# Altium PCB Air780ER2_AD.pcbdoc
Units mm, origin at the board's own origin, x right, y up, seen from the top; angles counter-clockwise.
Board outline 30.8 x 32.7 mm, 4 copper layers (Top Layer, 内层 2, 内层 3, Bottom Layer); 1 components, 0 nets, 54 pads, 0 vias.
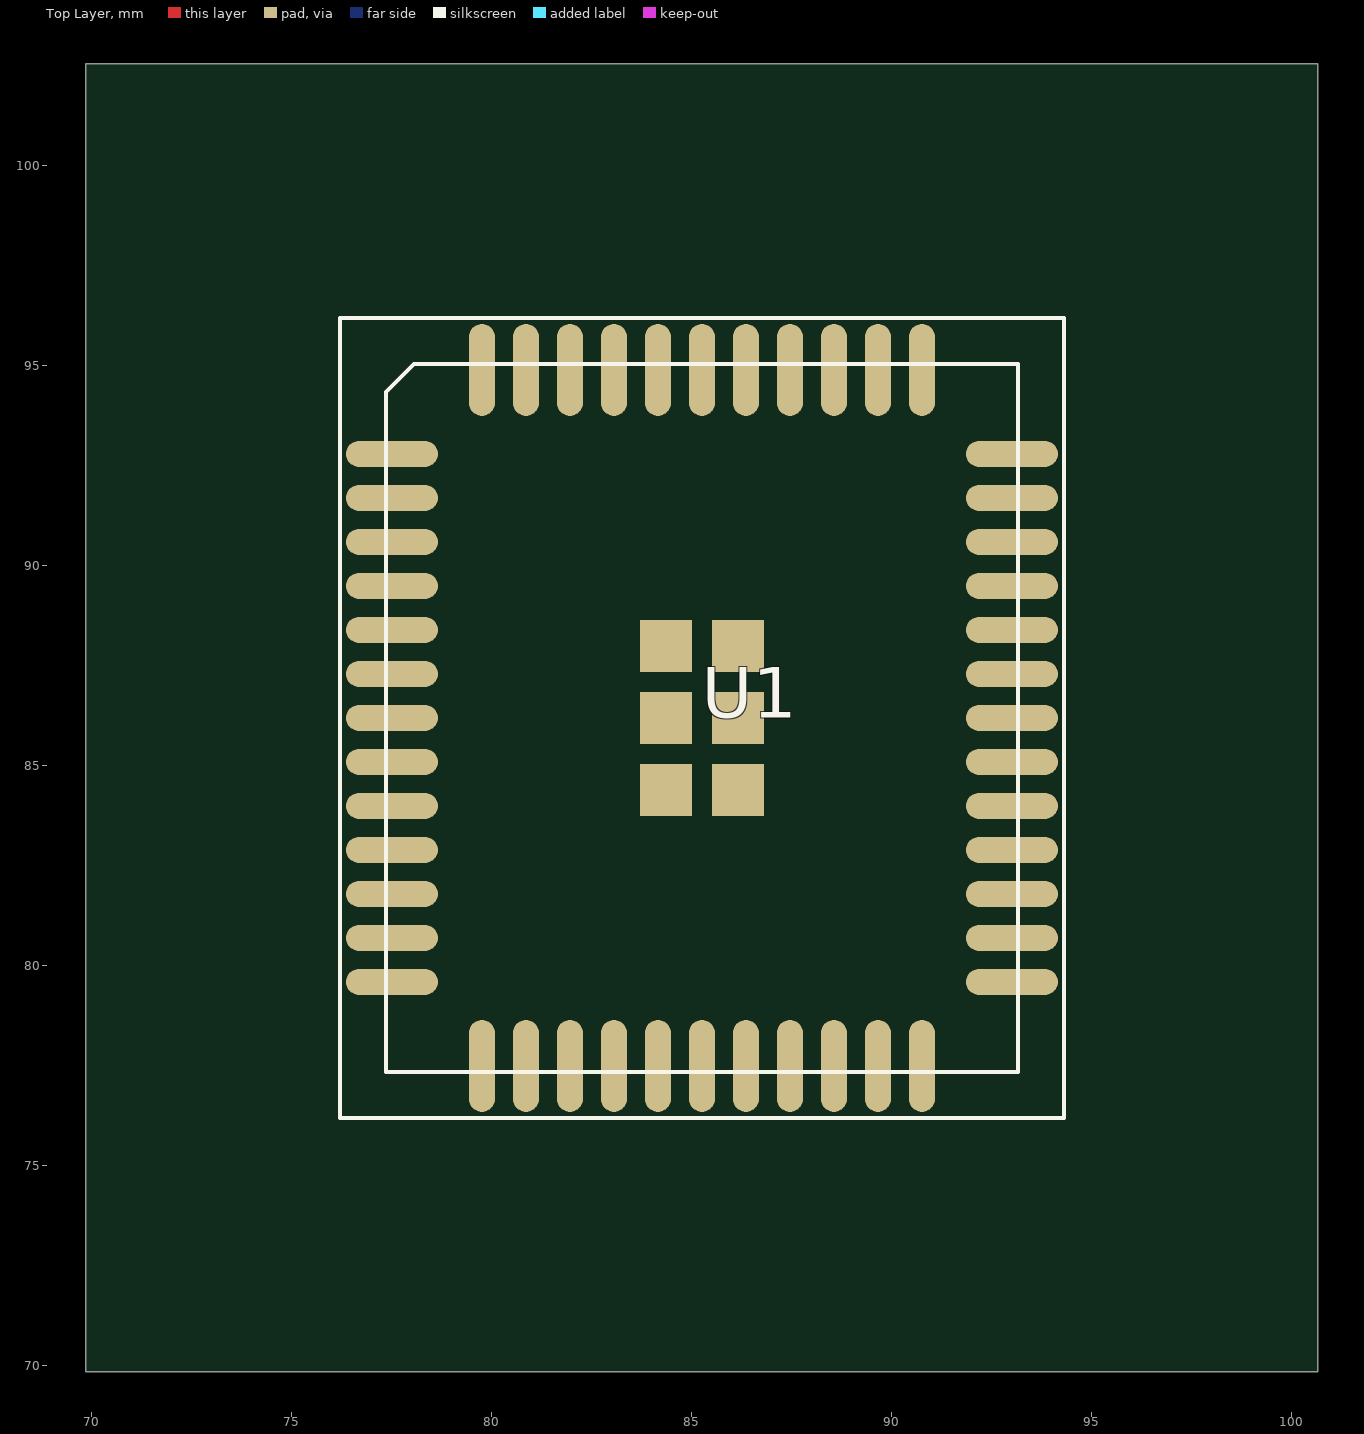
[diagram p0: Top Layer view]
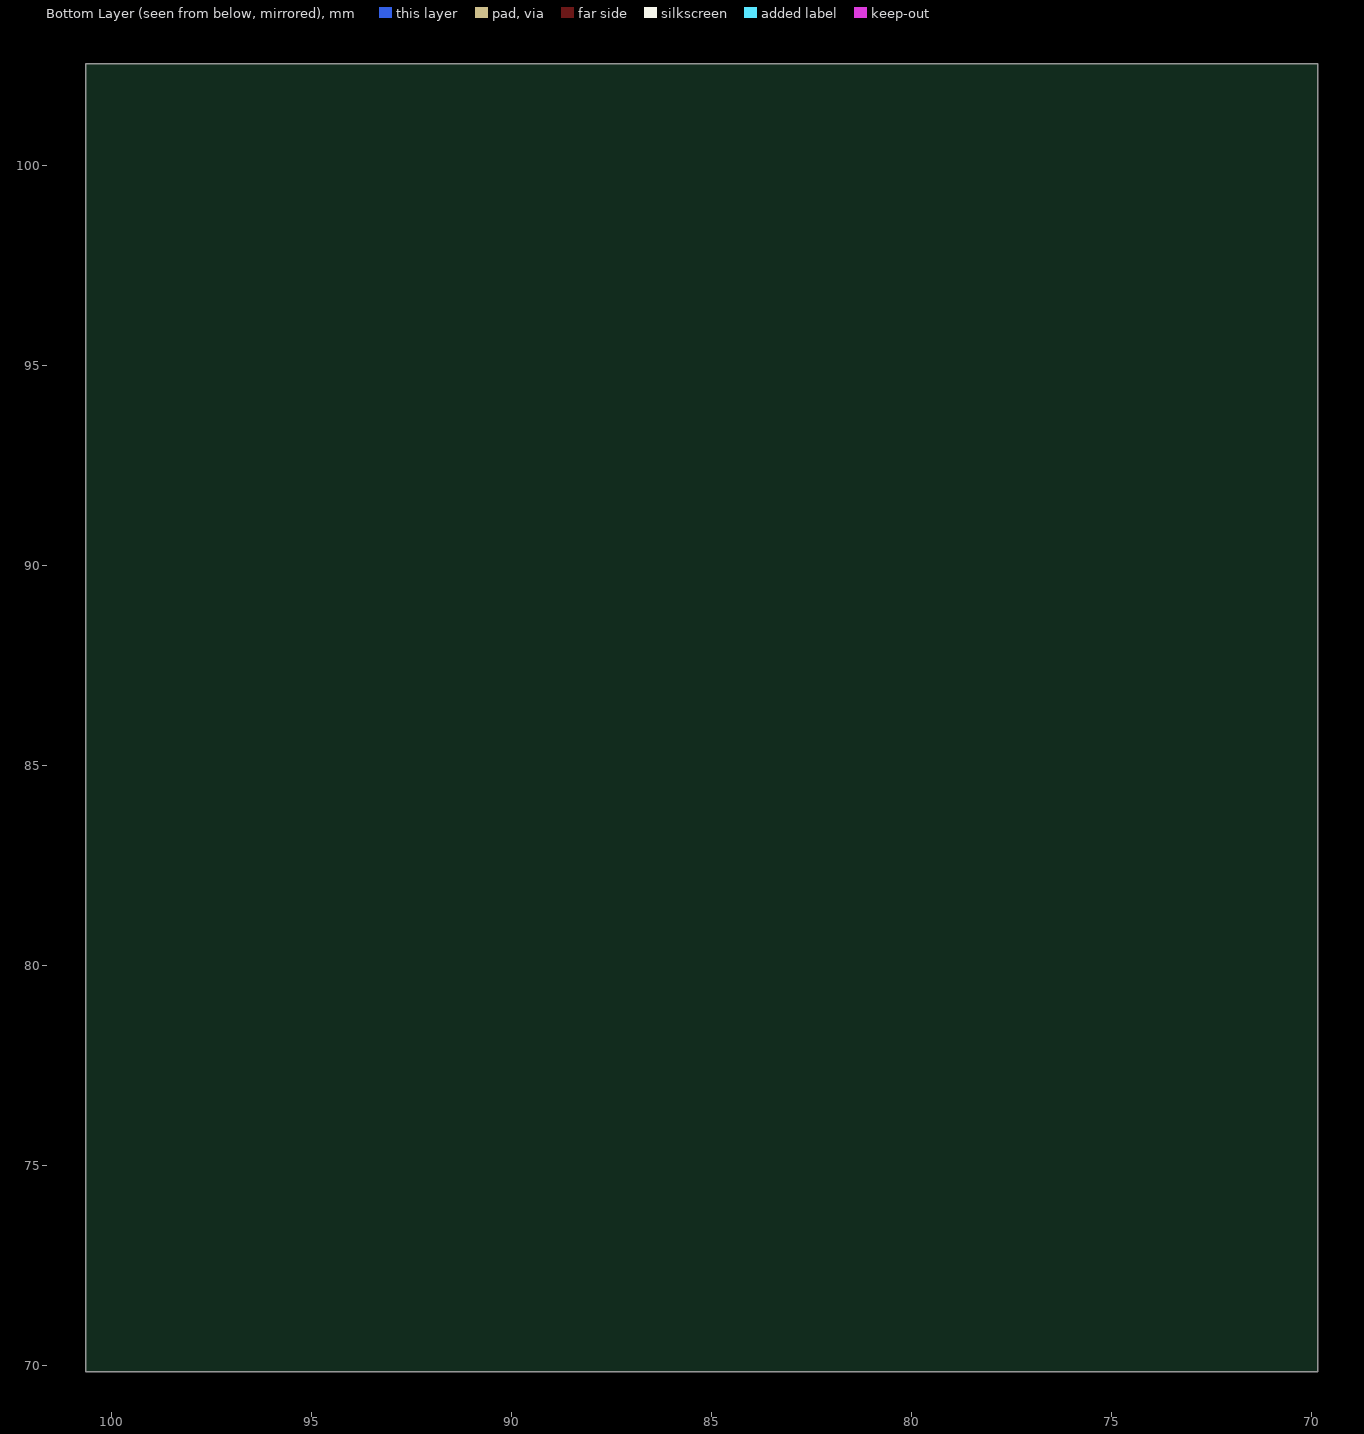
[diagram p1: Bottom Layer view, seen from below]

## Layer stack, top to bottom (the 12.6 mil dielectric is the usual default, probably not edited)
Top Layer: signal copper (thickness not stored)
Dielectric: dielectric 0.32, FR-4, Dk 4.8
内层 2: signal copper (thickness not stored)
Dielectric: dielectric 0.32, FR-4, Dk 4.8
内层 3: signal copper (thickness not stored)
Dielectric: dielectric 0.32, FR-4, Dk 4.8
Bottom Layer: signal copper (thickness not stored)

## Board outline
100.65,69.85 69.85,69.85 69.85,102.55 100.65,102.55

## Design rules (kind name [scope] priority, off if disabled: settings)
BoardOutlineClearance safeClearance [All] p0: genericclearance=0.254 ignorepadtopadclearanceinfootprint=FALSE except(0: Region-OutlineEdge Poly-OutlineEdge Text-OutlineEdge Sheet-OutlineEdge Hole-OutlineEdge Track-CutoutEdge SMDPad-CutoutEdge THPad-CutoutEdge Via-CutoutEdge Fill-CutoutEdge Region-CutoutEdge Poly-CutoutEdge Text-CutoutEdge Sheet-CutoutEdge Hole-CutoutEdge Arc-SplitContinuation Track-SplitContinuation SMDPad-SplitContinuation THPad-SplitContinuation Via-SplitContinuation Fill-SplitContinuation Poly-SplitContinuation Region-SplitContinuation Text-SplitContinuation; 0.152: Track-OutlineEdge SMDPad-OutlineEdge THPad-OutlineEdge Via-OutlineEdge Fill-OutlineEdge)
Clearance safeClearance [All] p1: gap=0.178 ignorepadtopadclearanceinfootprint=FALSE except(0: Region-Track Poly-Track Region-SMDPad Poly-SMDPad Region-THPad Poly-THPad Region-Via Poly-Via Region-Fill Poly-Fill Text-Fill Track-Region SMDPad-Region THPad-Region Via-Region Fill-Region Region-Region Poly-Region Text-Region Sheet-Region Hole-Region Track-Poly SMDPad-Poly THPad-Poly Via-Poly Fill-Poly Region-Poly Poly-Poly Text-Poly Sheet-Poly Hole-Poly Fill-Text Region-Text Poly-Text Text-Text Sheet-Text Hole-Text Region-Sheet Poly-Sheet Text-Sheet Sheet-Sheet Hole-Sheet Region-Hole Poly-Hole Text-Hole Sheet-Hole; 0.152: Track-Track SMDPad-Track THPad-Track Via-Track Fill-Track Text-Track Sheet-Track Hole-Track Track-SMDPad SMDPad-SMDPad THPad-SMDPad Via-SMDPad Fill-SMDPad Text-SMDPad Sheet-SMDPad Hole-SMDPad Track-THPad SMDPad-THPad THPad-THPad Via-THPad Fill-THPad Text-THPad Sheet-THPad Hole-THPad Track-Via SMDPad-Via THPad-Via Via-Via Fill-Via Text-Via Sheet-Via Hole-Via Track-Fill SMDPad-Fill THPad-Fill Via-Fill Fill-Fill Sheet-Fill Hole-Fill Track-Text SMDPad-Text THPad-Text Via-Text Track-Sheet SMDPad-Sheet THPad-Sheet Via-Sheet Fill-Sheet Track-Hole SMDPad-Hole THPad-Hole Via-Hole Fill-Hole Hole-Hole)
PasteMaskExpansion Common [All] p1: expansion=0
SolderMaskExpansion Common [All] p1: useseparateexpansions=TRUE expansion=0 expansionbottom=0
Width trackWidth [All] p1: maxlimit=12 minlimit=12 preferedwidth=12

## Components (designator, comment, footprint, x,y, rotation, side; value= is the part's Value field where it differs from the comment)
U1 "AIR780ER2" AIR780EX2 85.25,86.2 r0 top

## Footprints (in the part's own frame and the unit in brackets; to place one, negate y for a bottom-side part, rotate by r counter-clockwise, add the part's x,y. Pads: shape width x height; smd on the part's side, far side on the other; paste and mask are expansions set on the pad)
AIR780EX2 [mm]
  oval 2.3x0.65 smd: 1(-7.75,6.6) 2(-7.75,5.5) 3(-7.75,4.4) 4(-7.75,3.3) 5(-7.75,2.2) 6(-7.75,1.1) 7(-7.75,0) 8(-7.75,-1.1) 9(-7.75,-2.2) 10(-7.75,-3.3) 11(-7.75,-4.4) 12(-7.75,-5.5) 13(-7.75,-6.6) 23(7.75,-6.6) 24(7.75,-5.5) 25(7.75,-4.4) 26(7.75,-3.3) 27(7.75,-2.2) 28(7.75,-1.1) 29(7.75,0) 30(7.75,1.1) 31(7.75,2.2) 32(7.75,3.3) 33(7.75,4.4) 34(7.75,5.5) 35(7.75,6.6)
  oval 0.65x2.3 smd: 14(-4.4,-8.7) 15(-3.3,-8.7) 16(-2.2,-8.7) 17(-1.1,-8.7) 18(0,-8.7) 19(1.1,-8.7) 20(2.2,-8.7) 21(3.3,-8.7) 22(4.4,-8.7) 36(4.4,8.7) 37(3.3,8.7) 38(2.2,8.7) 39(1.1,8.7) 40(0,8.7) 41(-1.1,8.7) 42(-2.2,8.7) 43(-3.3,8.7) 44(-4.4,8.7) 95(-5.5,-8.7) 96(5.5,-8.7) 97(5.5,8.7) 98(-5.5,8.7)
  rect 1.3x1.3 smd: 89(-0.9,1.8) 90(-0.9,0) 91(-0.9,-1.8) 92(0.9,-1.8) 93(0.9,0) 94(0.9,1.8)
  silkscreen extent -9.05,-10 9.05,10

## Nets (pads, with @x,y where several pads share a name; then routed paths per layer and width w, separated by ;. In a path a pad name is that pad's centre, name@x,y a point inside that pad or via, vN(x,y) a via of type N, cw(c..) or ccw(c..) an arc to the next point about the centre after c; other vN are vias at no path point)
pads on no net: U1.1 U1.2 U1.3 U1.4 U1.5 U1.6 U1.7 U1.8 U1.9 U1.10 U1.11 U1.12 U1.13 U1.14 U1.15 U1.16 U1.17 U1.18 U1.19 U1.20 U1.21 U1.22 U1.23 U1.24 U1.25 U1.26 U1.27 U1.28 U1.29 U1.30 U1.31 U1.32 U1.33 U1.34 U1.35 U1.36 U1.37 U1.38 U1.39 U1.40 U1.41 U1.42 U1.43 U1.44 U1.89 U1.90 U1.91 U1.92 U1.93 U1.94 U1.95 U1.96 U1.97 U1.98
